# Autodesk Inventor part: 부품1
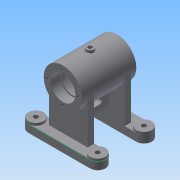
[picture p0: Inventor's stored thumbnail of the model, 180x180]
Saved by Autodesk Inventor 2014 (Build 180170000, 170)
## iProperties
Created: 2015-11
Part Number: 부품1
Material: 일반
Document SubType Name: Modeling
Designer: net
Density: 1 g/cm^3
Appearance: 기본값
Author: net
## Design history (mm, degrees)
sketch "스케치1"
  geometry: L1 (-40, -10)-(40, -10); L2 (40, 10)-(-40, 10); L3 (-40, -10)-(35.294, 8.824); L4 (40, -10)-(-40, 10); C1 r 3 at (-40, 0); C2 r 3 at (40, 0); A1 r 10 centre (-40, 0) between (-40, 10) and (-40, -10); A2 r 10 centre (40, 0) between (40, -10) and (40, 10); 1 further point
  constraints: 8 end point, 4 centre point, 4 point on circle, 2 coincident, 2 equal radius, 2 parallel, 2 tangent, 1 horizontal, 1 midpoint, 1 point on line
  dimensions: "d15" = 100 dimension on A2 A1; "d18" = 10 radius of A1; "d19" = 6 diameter of C1; "d20" = 151.928 deg angle of L3 L4; "d21" = 17.12016 distance from line of L3.end L4
extrude "돌출1" new body sketch "스케치1" distance "d22" = 10; taper "d23" = 0 deg
sketch "스케치2"
  geometry: C1 r 3 at (40, 0) reference; C2 r 3 at (-40, 0) reference; C3 r 10 at (-40, 0); C4 r 10 at (40, 0); A1 r 10 centre (-40, 0) between (-40, 10) and (-40, -10) reference; A2 r 10 centre (40, 0) between (40, -10) and (40, 10) reference; 1 further point
  constraints: 2 centre point, 2 coincident
  dimensions: "d24" = 20 diameter of C3; "d25" = 20 diameter of C4
extrude "돌출2" join sketch "스케치2" distance "d26" = 3; taper "d27" = 0 deg
sketch "스케치3"
  geometry: L1 (80, 0)-(0, 0) reference; L2 (15, 68)-(65, 68); L3 (65, 68)-(65, 0); L4 (65, 0)-(15, 0); L5 (15, 0)-(15, 68); 2 further points
  constraints: 8 end point, 2 midpoint, 2 parallel, 1 horizontal, 1 perpendicular
  dimensions: "d28" = 50 distance of L3.end L4.end; "d29" = 68 distance between parallel lines of L4 L2
extrude "돌출3" join sketch "스케치3" distance "d30" = 8; taper "d31" = 0 deg
sketch "스케치4"
  geometry: L1 (-40, -50)-(40, -50); L2 (40, -50)-(40, -70); L3 (40, -70)-(-40, -70); L4 (-40, -70)-(-40, -50); C1 r 3 at (-40, -60); C2 r 3 at (40, -60); 3 further points
  constraints: 8 end point, 2 centre point, 2 coincident, 2 midpoint, 2 parallel, 2 vertical alignment, 1 equal radius, 1 horizontal, 1 perpendicular, 4 other
  dimensions: "d34" = 80 distance between parallel lines of L2 L4; "d35" = 20 distance between parallel lines of L3 L1; "d36" = 40 distance from line of point (0, 0) L4 (= 0.5 x d34); "d37" = 50 distance from line of L1 point (0, 0); "d38" = 6 diameter of C1
extrude "돌출4" join sketch "스케치4" distance "d39" = 10; taper "d40" = 0 deg
sketch "스케치5"
  geometry: L1 (-40, -70)-(40, -70) reference; L2 (40, -50)-(-40, -50) reference; A1 r 10 centre (40, -60) between (40, -70) and (40, -50) reference; A2 r 10 centre (-40, -60) between (-40, -50) and (-40, -70) reference; 1 further point
extrude "돌출5" join sketch "스케치4" distance "d41" = 13; taper "d42" = 0 deg
extrude "돌출6" cut sketch "스케치4" stored distance "d43" = 13; taper "d44" = 0 deg
sketch "스케치6"
  geometry: L1 (0, 0)-(80, 0) reference; L2 (15, -68)-(65, -68); L3 (65, -68)-(65, 0); L4 (65, 0)-(15, 0); L5 (15, 0)-(15, -68); 1 further point
  constraints: 8 end point, 2 parallel, 1 horizontal, 1 perpendicular, 1 point on line
  dimensions: "d45" = 50 distance between parallel lines of L3 L5; "d46" = 68 distance between parallel lines of L2 L1; "d47" = 25 distance from line of point (40, 0) L5 (= 0.5 x d45)
extrude "돌출7" join sketch "스케치6" distance "d48" = 8; taper "d49" = 0 deg
node "작업 평면1"
sketch "스케치7"
  geometry: L1 (55, 0)-(55, -20) reference; L2 (68, -20)-(58, -20) reference; L3 (58, 0)-(58, -20) reference; L4 (58, 0)-(68, 0) reference; L5 (68, -20)-(68, 0) reference; L6 (68, 53)-(55, 53) reference; L7 (55, 60)-(55, 40) reference; L8 (68, 40)-(68, 60) reference; L9 (68, 40)-(58, 40) reference; L10 (58, 60)-(58, 40) reference; L11 (68, 60)-(58, 60) reference; L12 (35, -35.88)-(35, 72.577); L13 (58, 0)-(0, 0) reference; L14 (25, 0)-(25, 40); L15 (0, 40)-(58, 40) reference; L16 (45, 0)-(45, 40); L17 (25, 0)-(45, 0); L18 (25, 40)-(45, 40); L19 (35, 12.114)-(35, 28.114); L20 (38.5, 12.114)-(38.5, 28.114); L21 (31.5, 28.114)-(31.5, 12.114); A1 r 3.5 centre (35, 12.114) between (31.5, 12.114) and (38.5, 12.114); A2 r 3.5 centre (35, 28.114) between (38.5, 28.114) and (31.5, 28.114); 2 further points
  constraints: 18 end point, 6 point on line, 4 point on circle, 4 tangent, 3 vertical, 2 centre point, 2 horizontal, 1 midpoint, 1 parallel
  dimensions: "d50" = 33 distance between parallel lines of L8 L12; "d51" = 20 distance between parallel lines of L16 L14; "d52" = 10 distance between parallel lines of L12 L14 (= 0.5 x d51); "d53" = 12.57733 distance from line of L12.end L11; "d54" = 95.88048 distance from line of L12.start L11; "d55" = 3.5 radius of A2; "d56" = 23 dimension on A1 A2; "d57" = 31.88577 distance from line of L20.end L11
extrude "돌출8" join sketch "스케치7" stored distance "d58" = 8; taper "d59" = 0 deg
node "작업 평면2"
sketch "스케치8"
  geometry: L1 (0, -40)-(0, -48) reference; L2 (0, 0)-(0, 8) reference; L3 (-25, -55)-(0, -55); L4 (0, -55)-(0, 15); L5 (0, 15)-(-25, 15); L6 (-25, 15)-(-25, -55); L7 (45, 0)-(45, -40) reference; L8 (45, -20)-(-11.349, -20); L9 (68, -60)-(68, -40) reference; L10 (68, 0)-(68, 20) reference; 2 further points
  constraints: 10 end point, 2 horizontal, 2 midpoint, 2 parallel, 1 perpendicular, 1 point on line
  dimensions: "d60" = 70 distance of L5.end L3.start; "d61" = 25 distance of L3.start L3.end; "d62" = 56.34938 distance of L8.start L8.end; "d64" = 68 distance between parallel lines of L10 L4
revolve "회전1" sketch "스케치8" stored, may be unused: angle "d65" = 90 deg
node "작업 평면3"
sketch "스케치10"
  geometry: L1 (-83, -7)-(-83, 63) reference; L2 (-33, -7)-(-33, 63) reference; L3 (-33, -7)-(-83, -7) reference; L4 (-58, -7)-(-58, 63); L5 (-33, 63)-(-83, 63) reference; L6 (-58, 7)-(-79, 7); L7 (-79, 7)-(-79, 49); L8 (-79, 49)-(-58, 49); 1 further point
  constraints: 8 end point, 2 horizontal, 2 midpoint, 2 point on line, 1 vertical
  dimensions: "d72" = 42 distance between parallel lines of L8 L6; "d73" = 14 distance between parallel lines of L6 L3; "d74" = 42 diameter of L7 L4
revolve "회전2" sketch "스케치10" stored, may be unused: angle "d75" = 90 deg
hole "구멍1" diameter "d78" = 28; stored, may be unused: countersink angle "d82" = 90 deg, drill point angle "d84" = 0 deg; dims "d76" = 10, "d77" = 10, "d79" = 6, "d80" = 32, "d81" = 12, "d83" = 14
hole "구멍2" diameter "d87" = 28; stored, may be unused: countersink angle "d91" = 90 deg, drill point angle "d93" = 0 deg; dims "d85" = 10, "d86" = 10, "d88" = 6, "d89" = 32, "d90" = 12, "d92" = 14
node "작업 평면4"
sketch "스케치11"
  geometry: L1 (0, -50)-(0, -10) reference; C1 r 5 at (0, -30); 1 further point
  constraints: 1 centre point, 1 midpoint
  dimensions: "d95" = 10 diameter of C1
extrude "돌출9" join sketch "스케치11" stored distance "d96" = 8; taper "d97" = 0 deg
node "작업 평면5"
sketch "스케치12"
  geometry: L1 (40, -68)-(15, -68); L2 (40, -68)-(15.751, -54); C1 r 16 at (40, -68) reference; 1 further point
  constraints: 4 end point, 1 horizontal, 1 horizontal alignment
  dimensions: "d98" = 30 deg angle of L2 L1; "d99" = 28 distance of L1.start L2.end
  node "투영된 루프4"
node "작업 평면6"
sketch "스케치13"
  geometry: L1 (-35, 25)-(-35, -25) reference; C1 r 6 at (0, 0); 1 further point
  constraints: 1 centre point
  dimensions: "d100" = 12 diameter of C1; "d101" = 66.09085 distance of C1.centre point (-30, -58.89); "d102" = 35 distance from line of C1.centre L1
extrude "돌출10" join sketch "스케치13" stored distance "d103" = 8; taper "d104" = 0 deg
hole "구멍3" diameter "d107" = 4.917; stored, may be unused: countersink angle "d111" = 90 deg, drill point angle "d113" = 118 deg; dims "d105" = 10, "d106" = 10, "d108" = 6, "d109" = 32, "d110" = 12, "d112" = 14
hole "구멍4" diameter "d116" = 4.917; stored, may be unused: countersink angle "d120" = 90 deg, drill point angle "d122" = 118 deg; dims "d114" = 10, "d115" = 10, "d117" = 6, "d118" = 32, "d119" = 12, "d121" = 14
sketch "스케치14"
  geometry: C1 r 16 at (0, 0) reference; 2 further points
  constraints: 1 vertical alignment
  dimensions: "d123" = 20 distance of C1.centre point (0, 20)
hole "구멍5" sketch "스케치14" at (0, 20) diameter "d124" = 3.242; stored, may be unused: countersink angle "d128" = 90 deg, drill point angle "d130" = 118 deg; dims "d125" = 8, "d126" = 32, "d127" = 12, "d129" = 10
node "작업 평면7"
sketch "스케치15"
  geometry: C1 r 3 at (0, 0) reference; C2 r 10 at (0, 0) reference; 1 further point
node "솔리드1"
pattern_circular "원형 패턴1" dims angle "d132" = 360 deg
mirror "대칭1"
node "투영된 루프1"
node "투영된 루프2"
other parameters: "d94" = -96
